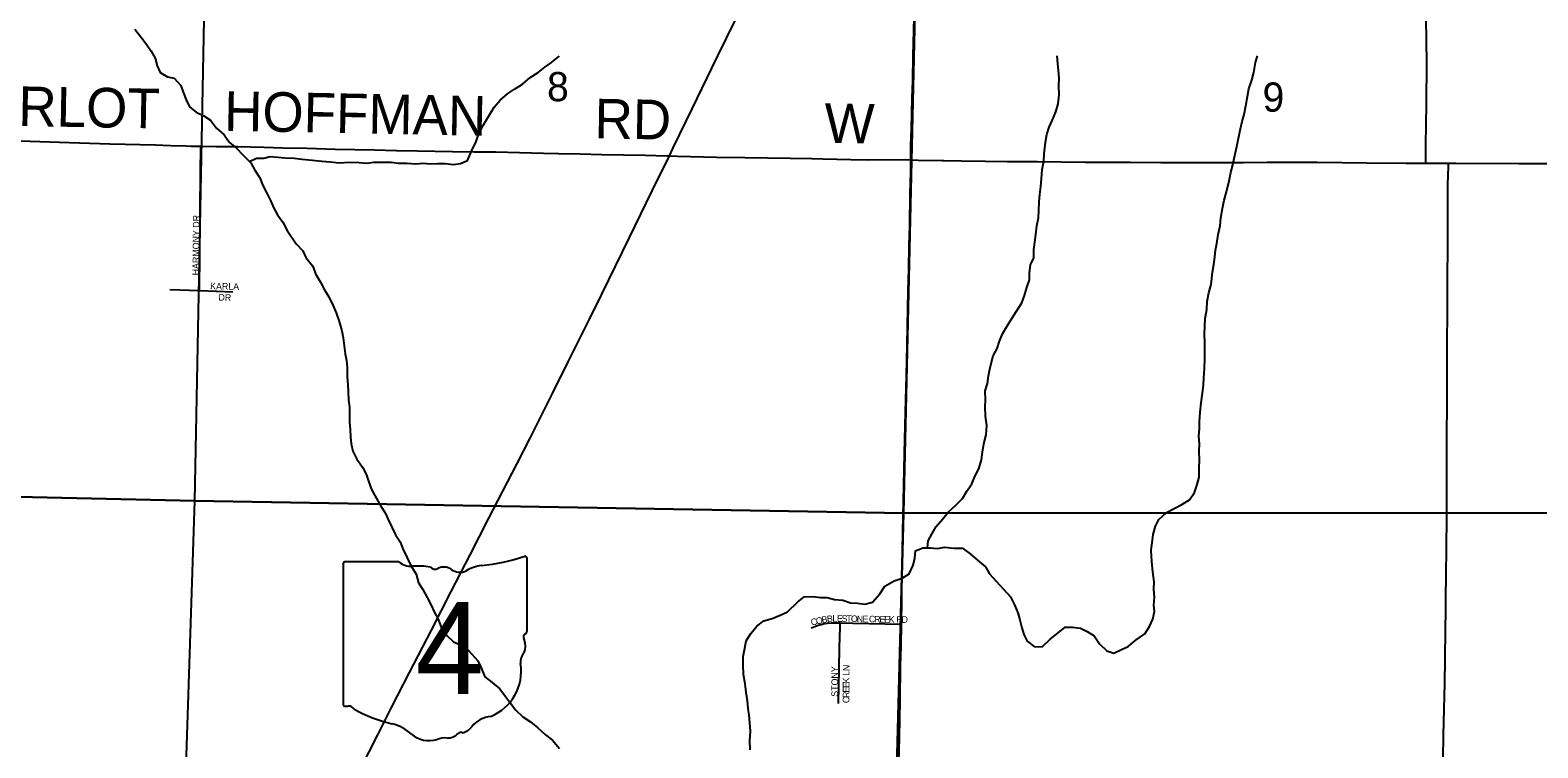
# Model space of a CAD drawing. Extents: x -9.1 to 34, y -3.1 to 22.
# Drawn here: x 2.915 to 5.075, y 15.416 to 16.445 of the extents above; entities that cross this region are included whole.
import ezdxf

# ---------------------------------------------------------------- set-up
doc = ezdxf.new("R2010")
doc.units = 0
for name, color, linetype in [('GM_X_County_Road', 7, 'Continuous'), ('GM_X_County_Road_Text', 7, 'Continuous'), ('GM_X_Minor_River', 7, 'Continuous'), ('GM_X_Section', 7, 'Continuous'), ('GM_X_Section_Text', 7, 'Continuous'), ('GM_X_State_Location', 7, 'Continuous'), ('GM_X_State_Route', 7, 'Continuous'), ('GM_X_State_Shield', 7, 'Continuous'), ('GM_X_Township_Subdivision', 7, 'Continuous'), ('GM_X_Township_Subdivision_Text', 7, 'Continuous')]:
    doc.layers.add(name, color=color, linetype=linetype)

msp = doc.modelspace()

# ---------------------------------------------------------------- linework, layer by layer
at = {"layer": 'GM_X_County_Road'}
for points in [[(4.18, 16.4081), (4.1925, 16.882), (4.1946, 16.8943), (4.1977, 16.9095), (4.206, 16.9459), (4.2107, 16.9671), (4.2192, 17.0035), (4.2265, 17.0337), (4.2354, 17.0731), (4.2381, 17.0844), (4.2385, 17.0869), (4.2388, 17.0887), (4.2389, 17.0911), (4.239, 17.0951)], [(4.9149, 16.2544), (4.9149, 16.2579), (4.9148, 16.2802), (4.9158, 16.3392), (4.9165, 16.3982), (4.9092, 16.8801)], [(4.1769, 16.2592), (4.177, 16.2794), (4.1775, 16.3042), (4.1787, 16.3477), (4.1795, 16.3726), (4.18, 16.4081)], [(2.6523, 16.2896), (2.6716, 16.2893), (2.7213, 16.2886), (2.7928, 16.2877), (2.8612, 16.2868), (2.914, 16.2859), (2.9854, 16.2836), (3.0289, 16.2821), (3.0941, 16.2804), (3.1159, 16.2797), (3.1376, 16.279), (3.1452, 16.2789)], [(3.1452, 16.2789), (3.1592, 16.2787)], [(3.1592, 16.2787), (3.1811, 16.2783), (3.2122, 16.278)], [(3.2122, 16.278), (3.2308, 16.2778), (3.2494, 16.2771), (3.2774, 16.2762), (3.3116, 16.2756), (3.352, 16.2745), (3.3799, 16.274), (3.4079, 16.2732), (3.439, 16.2726), (3.4405, 16.2726)], [(3.4405, 16.2726), (3.47, 16.2719), (3.5197, 16.2708), (3.5508, 16.2706), (3.5818, 16.2704), (3.616, 16.2696), (3.6501, 16.2688), (3.6718, 16.2682), (3.7029, 16.2676), (3.734, 16.2669), (3.765, 16.2662), (3.7961, 16.2656), (3.8271, 16.2649), (3.8308, 16.2648)], [(3.8308, 16.2648), (3.8426, 16.2644), (3.8612, 16.2638), (3.8984, 16.2631), (3.9388, 16.2625), (4.004, 16.2615), (4.035, 16.261), (4.0505, 16.2607), (4.0909, 16.2597), (4.1158, 16.2593), (4.1686, 16.2594), (4.1769, 16.2592)], [(4.1633, 15.5934), (4.1633, 15.5959), (4.1637, 15.627), (4.1641, 15.6581), (4.165, 15.6985), (4.1655, 15.7264), (4.1658, 15.7482), (4.1668, 15.7917), (4.1677, 15.8383), (4.1693, 15.8973), (4.1704, 15.95), (4.1715, 15.9936), (4.1724, 16.0464), (4.1731, 16.0713), (4.174, 16.1023), (4.1744, 16.1365), (4.1751, 16.1644), (4.1759, 16.211), (4.1767, 16.2421), (4.1769, 16.2576), (4.1769, 16.2592)], [(4.1769, 16.2592), (4.1874, 16.2588), (4.2215, 16.2581), (4.2239, 16.2581)], [(4.2239, 16.2581), (4.2494, 16.2576), (4.2836, 16.2571), (4.3149, 16.2567), (4.3581, 16.2566), (4.3923, 16.2563), (4.4265, 16.2559), (4.4545, 16.2557), (4.4793, 16.2556), (4.4917, 16.2555), (4.5352, 16.2553), (4.5756, 16.2552), (4.616, 16.2553), (4.6533, 16.2554), (4.6875, 16.2555), (4.7217, 16.2555), (4.759, 16.2555), (4.8304, 16.2549), (4.8864, 16.2545), (4.9149, 16.2544)], [(4.9149, 16.2544), (4.9237, 16.2544), (4.9471, 16.2542)], [(4.9437, 15.6283), (4.9437, 15.6314), (4.9439, 15.6625), (4.9445, 15.7029), (4.945, 15.7464), (4.9451, 15.7621), (4.9449, 15.7931), (4.9448, 15.8273), (4.945, 15.8678), (4.9454, 15.9051), (4.9452, 15.9175), (4.9452, 15.9331), (4.9453, 15.9611), (4.9456, 16.0046), (4.9457, 16.0325), (4.9458, 16.0543), (4.9459, 16.0852), (4.9461, 16.101), (4.9463, 16.1228), (4.9464, 16.1663), (4.9462, 16.1943), (4.9463, 16.216), (4.9464, 16.2255), (4.9466, 16.2345), (4.9471, 16.2516), (4.9471, 16.2542)], [(4.9471, 16.2542), (4.9578, 16.2541), (5.048, 16.2537), (5.0884, 16.2538)], [(4.9398, 15.2467), (4.9393, 15.2473), (4.9386, 15.2485), (4.938, 15.2498), (4.9377, 15.2511), (4.9374, 15.2527), (4.9375, 15.254), (4.9377, 15.2819), (4.9388, 15.3316), (4.9392, 15.3503), (4.9393, 15.3689), (4.9397, 15.4), (4.9403, 15.4341), (4.9419, 15.5086), (4.9423, 15.5428), (4.9432, 15.5863), (4.9436, 15.6124), (4.9437, 15.6283)], [(4.1594, 15.3947), (4.1603, 15.4313), (4.1613, 15.4841), (4.1621, 15.5338), (4.1628, 15.5618), (4.1633, 15.5934)]]:
    msp.add_lwpolyline(points, dxfattribs=at)
at = {"layer": 'GM_X_Minor_River'}
for points in [[(3.0649, 16.4466), (3.0734, 16.4355), (3.0808, 16.4255), (3.0882, 16.4151), (3.0937, 16.4048), (3.0965, 16.3937), (3.1009, 16.3842), (3.1114, 16.3783), (3.1212, 16.3763), (3.1305, 16.3655), (3.1341, 16.356), (3.1381, 16.3449), (3.1428, 16.335), (3.1525, 16.3272), (3.1634, 16.3221), (3.1731, 16.3159), (3.1816, 16.3043), (3.1928, 16.295), (3.2002, 16.2839), (3.2099, 16.2762), (3.2199, 16.2658), (3.2307, 16.255), (3.2366, 16.2443), (3.2436, 16.2331), (3.2479, 16.2221), (3.2542, 16.2102), (3.2589, 16.2007), (3.2637, 16.19), (3.2692, 16.1804), (3.2766, 16.1697), (3.2828, 16.1578), (3.2961, 16.1386), (3.3054, 16.1286), (3.3097, 16.119), (3.3197, 16.1064), (3.3237, 16.0957), (3.3307, 16.0838), (3.3366, 16.0727), (3.3428, 16.0628), (3.349, 16.0498), (3.353, 16.0395), (3.3577, 16.0272), (3.3613, 16.0139), (3.3634, 16.004), (3.3647, 15.9922), (3.366, 15.9808), (3.3682, 15.9713), (3.3688, 15.9619), (3.3689, 15.9486), (3.3698, 15.9364), (3.3704, 15.9266), (3.371, 15.9144), (3.3723, 15.9046), (3.3721, 15.8928), (3.3724, 15.8829), (3.3733, 15.8723), (3.3739, 15.8621), (3.3749, 15.8518), (3.3773, 15.8412), (3.3828, 15.8297), (3.3909, 15.8186), (3.3961, 15.8086), (3.3997, 15.7983), (3.4036, 15.7865), (3.411, 15.7735), (3.4172, 15.7624), (3.4235, 15.7528), (3.4279, 15.7432), (3.4334, 15.7314)], [(3.2291, 16.2566), (3.2388, 16.2617), (3.2493, 16.2615), (3.2588, 16.264), (3.2694, 16.263), (3.2796, 16.2621), (3.2932, 16.2615), (3.3038, 16.2598), (3.3192, 16.2588), (3.3328, 16.2574), (3.3453, 16.2564), (3.3574, 16.2547), (3.3721, 16.2556), (3.3861, 16.2553), (3.3974, 16.2544), (3.4073, 16.2557), (3.4201, 16.2559), (3.4322, 16.2557), (3.4424, 16.2544), (3.4545, 16.2541), (3.4673, 16.2532), (3.4779, 16.2541), (3.4885, 16.2532), (3.4987, 16.2538), (3.5097, 16.2536), (3.521, 16.2526), (3.5316, 16.254), (3.5415, 16.2583), (3.5474, 16.2726), (3.5537, 16.2854), (3.5573, 16.2952), (3.5643, 16.3091), (3.5728, 16.3234), (3.5798, 16.3346), (3.5883, 16.3447), (3.5987, 16.3536), (3.609, 16.3603), (3.6201, 16.3677), (3.6312, 16.377), (3.6427, 16.3843), (3.6522, 16.3921), (3.6618, 16.3988), (3.6722, 16.407), (3.673, 16.4081)], [(4.2006, 15.7028), (4.2016, 15.7128), (4.2075, 15.7233), (4.2129, 15.7335), (4.2226, 15.7443), (4.2307, 15.7544), (4.2407, 15.7637), (4.2506, 15.7734), (4.2569, 15.7839), (4.2642, 15.7944), (4.2686, 15.8049), (4.274, 15.8162), (4.278, 15.829), (4.2797, 15.84), (4.2814, 15.8521), (4.2847, 15.8649), (4.2857, 15.8782), (4.2836, 15.8915), (4.2831, 15.9047), (4.2836, 15.9146), (4.2835, 15.9279), (4.2867, 15.9384), (4.288, 15.9494), (4.2904, 15.9611), (4.2949, 15.9781), (4.3007, 15.9886), (4.3039, 15.9991), (4.3083, 16.0097), (4.3145, 16.0202), (4.3215, 16.0318), (4.3281, 16.0419), (4.3358, 16.0539), (4.3398, 16.0645), (4.343, 16.0758), (4.3466, 16.0871), (4.3467, 16.0966), (4.3485, 16.1083), (4.3532, 16.1188), (4.353, 16.1306), (4.3543, 16.1412), (4.356, 16.1522), (4.3573, 16.1646), (4.3598, 16.176), (4.3603, 16.1866), (4.3605, 16.1987), (4.3618, 16.2093), (4.3632, 16.221), (4.3641, 16.2316), (4.3651, 16.2452), (4.3676, 16.2573), (4.3677, 16.2676), (4.3699, 16.2846), (4.3716, 16.2955), (4.3752, 16.3061), (4.3799, 16.3166), (4.3846, 16.3279), (4.3878, 16.3392), (4.3892, 16.3521), (4.389, 16.365), (4.3892, 16.3764), (4.3886, 16.387), (4.3873, 16.3972), (4.3863, 16.4081)], [(4.6611, 16.361), (4.6655, 16.3735), (4.6683, 16.3844), (4.6708, 16.3984), (4.6736, 16.4081)], [(4.2049, 15.7029), (4.2147, 15.702), (4.2257, 15.7037), (4.2377, 15.7023), (4.2506, 15.7025), (4.2618, 15.694), (4.2722, 15.6851), (4.2838, 15.6754), (4.2897, 15.6654), (4.2993, 15.655), (4.3097, 15.6435), (4.3198, 15.6323), (4.3252, 15.6212), (4.3303, 15.6094), (4.3332, 15.5995), (4.3357, 15.5881), (4.3389, 15.5785), (4.3437, 15.569), (4.3537, 15.5612), (4.3651, 15.561), (4.3766, 15.5718), (4.3881, 15.5807), (4.398, 15.5889), (4.4086, 15.5891), (4.42, 15.5877), (4.4297, 15.5827), (4.4394, 15.5764), (4.4472, 15.5653), (4.4576, 15.5553), (4.4677, 15.5517), (4.4788, 15.5572), (4.4883, 15.5615), (4.4998, 15.5708), (4.5121, 15.5793), (4.519, 15.5902), (4.5238, 15.6007), (4.5258, 15.6113), (4.5248, 15.6208), (4.5258, 15.6322), (4.5252, 15.6432), (4.5254, 15.6542), (4.5241, 15.6644), (4.5224, 15.6773), (4.5218, 15.6902), (4.5212, 15.7001), (4.5225, 15.7099), (4.5243, 15.722), (4.5275, 15.7337), (4.5322, 15.7435), (4.5433, 15.7535), (4.554, 15.759), (4.565, 15.7649), (4.5761, 15.7715), (4.5831, 15.782), (4.5871, 15.7937), (4.5899, 15.8043), (4.5901, 15.8168), (4.5907, 15.8285), (4.5898, 15.8418), (4.5903, 15.852), (4.5897, 15.8627), (4.5907, 15.8736), (4.5905, 15.8835), (4.5914, 15.8975), (4.5928, 15.9108), (4.5949, 15.9247), (4.5962, 15.9365), (4.5968, 15.9463), (4.5974, 15.96), (4.598, 15.974), (4.5982, 15.9869), (4.598, 15.9971), (4.5975, 16.0092), (4.598, 16.0206), (4.5986, 16.0316), (4.6011, 16.0444), (4.6013, 16.0558), (4.6037, 16.0686), (4.6073, 16.0803), (4.6091, 16.0981), (4.6112, 16.1091), (4.6125, 16.1197), (4.6134, 16.1295), (4.6151, 16.1393), (4.6172, 16.1522), (4.6201, 16.1646), (4.621, 16.176), (4.6235, 16.1892), (4.6256, 16.2013), (4.6292, 16.2134), (4.6329, 16.2289), (4.6353, 16.2409), (4.6382, 16.2519), (4.641, 16.2651), (4.6439, 16.278), (4.6488, 16.3014), (4.6517, 16.3142), (4.6545, 16.324), (4.657, 16.3365), (4.6591, 16.3497), (4.6611, 16.361)], [(3.4334, 15.7314), (3.4381, 15.7215), (3.4447, 15.7115), (3.4487, 15.7012), (3.455, 15.6886), (3.4601, 15.6775), (3.4678, 15.6652), (3.4714, 15.6527), (3.4776, 15.6431), (3.4835, 15.6316), (3.489, 15.6217), (3.4941, 15.6102), (3.4992, 15.6006), (3.5043, 15.5877), (3.5117, 15.5773), (3.5214, 15.568), (3.5315, 15.5637), (3.5435, 15.5551), (3.5561, 15.5409), (3.5608, 15.5306), (3.5663, 15.518), (3.5767, 15.5095), (3.5879, 15.5005), (3.5961, 15.4898), (3.6031, 15.4802), (3.6105, 15.4698), (3.6205, 15.4606), (3.6318, 15.4535), (3.6422, 15.4446), (3.6534, 15.4346), (3.6631, 15.4268), (3.6731, 15.4149)], [(3.9464, 15.4132), (3.9458, 15.4261), (3.9472, 15.4397), (3.9459, 15.4519), (3.9449, 15.4629), (3.9436, 15.4724), (3.9426, 15.4834), (3.9406, 15.4956), (3.9393, 15.5077), (3.9372, 15.5214), (3.9363, 15.5351), (3.9365, 15.5468), (3.939, 15.5589), (3.941, 15.5695), (3.9473, 15.58), (3.9561, 15.5905), (3.9661, 15.5983), (3.9782, 15.6015), (3.9897, 15.6062), (3.9999, 15.6109), (4.0142, 15.6251), (4.0237, 15.6325), (4.0366, 15.633), (4.0472, 15.6317), (4.057, 15.6316), (4.0672, 15.6287), (4.0792, 15.6278), (4.0905, 15.6241), (4.1003, 15.6232), (4.1109, 15.6219), (4.1219, 15.6251), (4.1323, 15.6367), (4.1393, 15.6476), (4.1527, 15.6553), (4.1644, 15.6593), (4.1744, 15.6655), (4.1803, 15.6779), (4.1827, 15.6878), (4.1836, 15.6987), (4.1939, 15.7027), (4.2049, 15.7029)]]:
    msp.add_lwpolyline(points, dxfattribs=at)
at = {"layer": 'GM_X_Section'}
for points in [[(2.6, 15.7826), (3.1506, 15.7703), (3.1704, 16.7805), (2.6, 16.7869)], [(2.6, 14.7785), (3.1179, 14.7624), (3.1506, 15.7703), (2.6, 15.7826)]]:
    msp.add_lwpolyline(points, dxfattribs=at)
for points in [[(3.1704, 16.7805), (4.189, 16.7633), (4.1665, 15.7524), (3.1506, 15.7703)], [(4.189, 16.7633), (5.2164, 16.757), (5.2057, 15.7528), (4.1665, 15.7524)], [(3.1506, 15.7703), (4.1665, 15.7524), (4.1399, 14.7501), (3.1179, 14.7624)], [(4.1665, 15.7524), (5.2057, 15.7528), (5.1863, 14.7444), (4.1399, 14.7501)]]:
    msp.add_lwpolyline(points, close=True, dxfattribs=at)
at = {"layer": 'GM_X_State_Route'}
for points in [[(3.9003, 16.4081), (4.1488, 16.9151), (4.1855, 16.9883), (4.2017, 17.0206), (4.2242, 17.0649), (4.239, 17.0951), (4.2434, 17.104), (4.2483, 17.1139)], [(3.3874, 15.3851), (3.4132, 15.4356), (3.4327, 15.4737), (3.4585, 15.5241), (3.4898, 15.5848), (3.5181, 15.6401), (3.5452, 15.6926), (3.5721, 15.7451), (3.612, 15.8225), (3.6315, 15.8612), (3.6638, 15.9249), (3.6859, 15.9694), (3.7161, 16.0307), (3.7338, 16.0667), (3.7736, 16.1478), (3.8063, 16.2148), (3.8308, 16.2648), (3.8363, 16.2762), (3.8635, 16.332), (3.8918, 16.3903), (3.9003, 16.4081)]]:
    msp.add_lwpolyline(points, dxfattribs=at)
at = {"layer": 'GM_X_State_Shield'}
for p, q in [((3.6267, 15.5829), (3.6267, 15.6876)), ((3.363, 15.6792), (3.363, 15.4791)), ((3.4428, 15.6826), (3.3656, 15.6826)), ((3.6267, 15.5829), (3.6267, 15.5829))]:
    msp.add_line(p, q, dxfattribs=at)
for centre, radius, start, end in [((3.5328, 15.9555), 0.2796, 275.8445, 288.9065), ((3.6238, 15.688), 0.00294, 351.8621, 97.738), ((3.366, 15.6796), 0.00305, 98.1301, 188.1301), ((3.4612, 15.7059), 0.0296, 231.6195, 271.1119), ((3.471, 15.5703), 0.1064, 80.4867, 94.9883), ((3.4952, 15.6807), 0.00855, 219.7921, 297.1024), ((3.5077, 15.6575), 0.0178, 54.4667, 119.1411), ((3.5307, 15.6892), 0.0214, 233.8562, 294.8282), ((3.5684, 15.6215), 0.0563, 97.3462, 120.7689), ((3.626, 15.5752), 0.00454, 107.944, 210.337), ((3.6235, 15.5825), 0.00314, 289.6038, 7.7341), ((3.5971, 15.562), 0.0273, 340.033, 23.6496), ((3.5484, 15.5258), 0.0699, 292.3089, 8.9858), ((3.6372, 15.5391), 0.0198, 136.8065, 186.9296), ((3.3661, 15.4786), 0.00308, 171.9584, 258.3066), ((3.3665, 15.4991), 0.0235, 267.339, 280.6039), ((3.3713, 15.4675), 0.00848, 29.7484, 93.2717), ((3.4784, 15.6473), 0.2019, 240.4129, 257.1985), ((3.4182, 15.3892), 0.0632, 47.1842, 75.836), ((3.5779, 15.4229), 0.0383, 94.4031, 142.5768), ((3.4865, 15.4665), 0.0401, 230.7004, 286.2918), ((3.5097, 15.3973), 0.0329, 85.6951, 111.2099), ((3.5126, 15.4515), 0.0214, 268.777, 315.5493), ((3.5319, 15.4322), 0.00601, 65.7517, 132.6484), ((3.5294, 15.4597), 0.0226, 282.8732, 323.2771)]:
    msp.add_arc(centre, radius, start, end, dxfattribs=at)
at = {"layer": 'GM_X_Township_Subdivision'}
for points in [[(3.1572, 16.0717), (3.1573, 16.0767), (3.1574, 16.0829), (3.1576, 16.1139), (3.1588, 16.2471), (3.1591, 16.2719), (3.1592, 16.2787)], [(3.1147, 16.073), (3.1572, 16.0717)], [(3.1572, 16.0717), (3.1583, 16.0717), (3.2051, 16.07)], [(4.0339, 15.588), (4.0367, 15.5892), (4.0424, 15.5912), (4.0483, 15.5929), (4.0512, 15.5936), (4.0542, 15.5942), (4.0572, 15.5946), (4.0632, 15.5952), (4.0724, 15.5954), (4.0754, 15.5953)], [(4.0732, 15.4797), (4.0735, 15.5045), (4.074, 15.5294), (4.0747, 15.5604), (4.0753, 15.5884), (4.0754, 15.5953)], [(4.0754, 15.5953), (4.0938, 15.5949), (4.1398, 15.5939), (4.1599, 15.5935), (4.1633, 15.5934)]]:
    msp.add_lwpolyline(points, dxfattribs=at)

# ---------------------------------------------------------------- texts
at = {"layer": 'GM_X_County_Road_Text'}
for s, height, rotation, p in [('SOMERLOT', 0.05682, 358.986, (2.6736, 16.3116)), ('HOFFMAN', 0.05682, 358.8819, (3.1922, 16.3008)), ('RD', 0.05682, 359.0267, (3.7231, 16.2899)), ('W', 0.0568, 359.2752, (4.0528, 16.2833))]:
    msp.add_text(s, height=height, rotation=rotation, dxfattribs=at).set_placement(p)
at = {"layer": 'GM_X_Section_Text'}
for s, p in [('8', (3.6554, 16.3431)), ('9', (4.6808, 16.3281))]:
    msp.add_text(s, height=0.0419, rotation=0, dxfattribs=at).set_placement(p)
at = {"layer": 'GM_X_State_Location'}
for s in ['s', 'r']:
    msp.add_text(s, height=0.000189, dxfattribs=at).set_placement((3.4919, 15.5658))
msp.add_text('4', height=0.000189, rotation=0, dxfattribs=at).set_placement((3.4633, 15.552))
at = {"layer": 'GM_X_State_Shield'}
msp.add_text('4', height=0.1318, dxfattribs=at).set_placement((3.4668, 15.4932))
at = {"layer": 'GM_X_Township_Subdivision_Text'}
for s, rotation, p in [('HARMONY DR', 89.3972, (3.1566, 16.0934)), ('KARLA', 358.8072, (3.1725, 16.0734)), ('DR', 356.989, (3.1843, 16.0575)), ('C', 13.8301, (4.0346, 15.591)), ('O', 13.0077, (4.0418, 15.5928)), ('B', 10.1571, (4.0498, 15.5946)), ('B', 6.646, (4.057, 15.5959)), ('L', 359.6448, (4.0642, 15.5968)), ('E', 359.0984, (4.0708, 15.5967)), ('S', 359.0165, (4.0775, 15.5966)), ('T', 359.0279, (4.0842, 15.5965)), ('O', 359.0164, (4.0908, 15.5964)), ('N', 359.0244, (4.0992, 15.5963)), ('E', 359.0416, (4.1075, 15.5961)), ('C', 359.0286, (4.1167, 15.596)), ('R', 359.0043, (4.1242, 15.5958)), ('E', 359.0279, (4.1317, 15.5957)), ('E', 359.0165, (4.1383, 15.5956)), ('K', 359.0244, (4.145, 15.5955)), ('R', 359.4597, (4.1559, 15.5953)), ('D', 359.9703, (4.1635, 15.5952)), ('STONY', 90, (4.0724, 15.4893)), ('K', 89.9126, (4.0887, 15.5084)), ('L', 89.0711, (4.0887, 15.5192)), ('N', 86.5014, (4.0888, 15.5258)), ('E', 90, (4.0887, 15.5018)), ('E', 90, (4.0887, 15.4951)), ('R', 90, (4.0887, 15.4876)), ('C', 90, (4.0887, 15.4801))]:
    msp.add_text(s, height=0.00947, rotation=rotation, dxfattribs=at).set_placement(p)

doc.saveas('drawing.dxf')
